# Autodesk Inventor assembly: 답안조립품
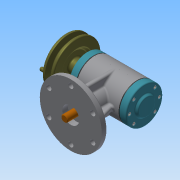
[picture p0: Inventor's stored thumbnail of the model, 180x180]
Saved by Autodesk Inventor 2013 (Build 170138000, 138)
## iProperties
Created: 2019-11
Part Number: 답안조립품
Document SubType Name: Assembly
Designer: Administrator
Author: Administrator
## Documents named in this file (18)
- C:\Users\Administrator\Desktop\391104v1017\답안조립품.iam
- C:\Users\Administrator\Desktop\391104v1017\본체.ipt
- C:\Users\Administrator\Desktop\391104v1017\V-벨트풀리.ipt
- C:\Users\Administrator\Desktop\391104v1017\개스킷.ipt
- C:\Users\Administrator\Desktop\391104v1017\뒤커버.ipt
- C:\Users\Administrator\Desktop\391104v1017\멈춤나사 M3x8.ipt
- C:\Users\Administrator\Desktop\391104v1017\베어링 6201.ipt
- C:\Users\Administrator\Desktop\391104v1017\베어링 6202.ipt
- C:\Users\Administrator\Desktop\391104v1017\본체커버.ipt
- C:\Users\Administrator\Desktop\391104v1017\볼트 M3x0.5x8.ipt
- C:\Users\Administrator\Desktop\391104v1017\슬라이드.ipt
- C:\Users\Administrator\Desktop\391104v1017\앞커버.ipt
- C:\Users\Administrator\Desktop\391104v1017\오일 실 12 22 7.ipt
- 오일 실 12 22 7.ipt
- C:\Users\Administrator\Desktop\391104v1017\키 4x4x18.ipt
- 키 4x4x18.ipt
- C:\Users\Administrator\Desktop\391104v1017\편심축.ipt
- C:\Users\Administrator\Desktop\391104v1017\스프링.ipt
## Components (3 placed, 2 different names)
1. V-벨트풀리:1
2. 개스킷:1
3. 개스킷:2
